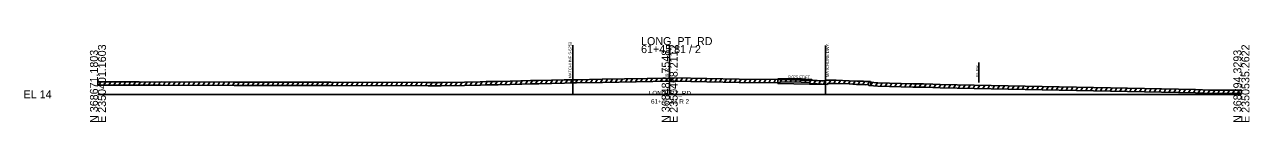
# Model space of a CAD drawing. Extents: x 974 to 2350744, y -10 to 368509.
# Drawn here: x 1974.3 to 2402.8, y 5990.3 to 6020.1 of the extents above; entities that cross this region are included whole.
import ezdxf

# ---------------------------------------------------------------- set-up
doc = ezdxf.new("R2010")
doc.units = 0
for name, color, linetype in [('RD_GPK_XS_Cell', 7, 'Continuous'), ('RD_XS_Base', 7, 'Continuous'), ('RD_XS_ExGround', 7, 'Continuous'), ('RD_XS_ExPaveRet', 7, 'Continuous'), ('RD_XS_ExRW', 7, 'Continuous'), ('RD_XS_MatchLine', 7, 'Continuous'), ('RD_XS_Pave', 7, 'Continuous'), ('RD_XS_TX_Elev_EX', 7, 'Continuous'), ('RD_XS_TX_Slope', 7, 'Continuous'), ('RD_XS_TX_Station', 7, 'Continuous')]:
    doc.layers.add(name, color=color, linetype=linetype)

msp = doc.modelspace()

# ---------------------------------------------------------------- linework, layer by layer
at = {"layer": 'RD_GPK_XS_Cell'}
for p, q in [((2200, 6000), (2200, 6017.25)), ((2000, 6000), (2200, 6000)), ((2200, 6000), (2400, 6000))]:
    msp.add_line(p, q, dxfattribs=at)
at = {"layer": 'RD_XS_Base'}
for p, q in [((2237.82, 6003.82), (2237.82, 6005.16)), ((2237.82, 6003.82), (2254.52, 6003.41)), ((2254.52, 6003.41), (2254.52, 6004.75))]:
    msp.add_line(p, q, dxfattribs=at)
at = {"layer": 'RD_XS_ExGround'}
msp.add_lwpolyline([(2000, 6004.41), (2007.21, 6004.37), (2014.41, 6004.37), (2015.38, 6004.31), (2022.11, 6004.38), (2047.62, 6004.26), (2053.58, 6004.25), (2057.29, 6004.24), (2080.97, 6004.21), (2081.44, 6004.21), (2115.47, 6004.12), (2120.02, 6004.16), (2128.26, 6004.3), (2133.76, 6004.38), (2135.8, 6004.48), (2139.62, 6004.5), (2140, 6004.51), (2144.22, 6004.58), (2147.95, 6004.68), (2148.26, 6004.7), (2151.36, 6004.81), (2154.18, 6004.86), (2163.15, 6005.08), (2165.49, 6005.14), (2167.39, 6005.14), (2176.43, 6005.3), (2200, 6005.72), (2201.67, 6005.75), (2224.34, 6005.29), (2237.82, 6005.16), (2237.98, 6005.46), (2238.34, 6005.46), (2241.38, 6005.48), (2246.08, 6005.4), (2249.32, 6005.24), (2249.68, 6005.24), (2249.84, 6004.94), (2251.62, 6004.83), (2254.52, 6004.67), (2254.68, 6004.97), (2255.03, 6004.97), (2256.6, 6004.95), (2258.25, 6004.92), (2262.79, 6004.79), (2265.42, 6004.64), (2267.84, 6004.6), (2268.58, 6004.53), (2269.1, 6004.55), (2269.87, 6004.52), (2270.24, 6004.51), (2270.4, 6004.21), (2271.42, 6004.15), (2272.85, 6004.05), (2285.05, 6003.69), (2286.57, 6003.65), (2288.8, 6003.63), (2292.09, 6003.51), (2294.62, 6003.45), (2384, 6001.69), (2388.96, 6001.47), (2392.65, 6001.47), (2400, 6001.43)], dxfattribs=at)
at = {"layer": 'RD_XS_ExPaveRet'}
for p, q in [((2000, 6003.27), (2000, 6004.41)), ((2000.38, 6003.26), (2001.04, 6004.4)), ((2002.11, 6003.26), (2002.77, 6004.4)), ((2003.84, 6003.25), (2004.5, 6004.39)), ((2005.56, 6003.24), (2006.22, 6004.38)), ((2007.29, 6003.23), (2007.95, 6004.37)), ((2009.02, 6003.23), (2009.68, 6004.37)), ((2010.75, 6003.23), (2011.41, 6004.37)), ((2012.49, 6003.23), (2013.15, 6004.37)), ((2014.22, 6003.23), (2014.86, 6004.34)), ((2015.92, 6003.18), (2016.58, 6004.33)), ((2017.66, 6003.19), (2018.33, 6004.34)), ((2019.41, 6003.21), (2020.07, 6004.36)), ((2021.15, 6003.23), (2021.81, 6004.38)), ((2022.88, 6003.24), (2023.54, 6004.38)), ((2024.61, 6003.23), (2025.27, 6004.37)), ((2026.34, 6003.22), (2027, 6004.36)), ((2028.07, 6003.21), (2028.72, 6004.35)), ((2029.79, 6003.2), (2030.45, 6004.34)), ((2031.52, 6003.2), (2032.18, 6004.34)), ((2033.25, 6003.19), (2033.91, 6004.33)), ((2034.98, 6003.18), (2035.63, 6004.32)), ((2036.7, 6003.17), (2037.36, 6004.31)), ((2038.43, 6003.16), (2039.09, 6004.3)), ((2040.16, 6003.16), (2040.82, 6004.3)), ((2041.89, 6003.15), (2042.54, 6004.29)), ((2043.61, 6003.14), (2044.27, 6004.28)), ((2045.34, 6003.13), (2046, 6004.27)), ((2047.07, 6003.12), (2047.73, 6004.26)), ((2048.8, 6003.12), (2049.46, 6004.26)), ((2050.53, 6003.11), (2051.18, 6004.25)), ((2052.26, 6003.11), (2052.91, 6004.25)), ((2053.98, 6003.1), (2054.64, 6004.25)), ((2055.72, 6003.1), (2056.37, 6004.24)), ((2057.45, 6003.1), (2058.11, 6004.24)), ((2059.18, 6003.1), (2059.84, 6004.24)), ((2060.91, 6003.09), (2061.57, 6004.24)), ((2062.64, 6003.09), (2063.3, 6004.23)), ((2064.37, 6003.09), (2065.03, 6004.23)), ((2066.1, 6003.09), (2066.76, 6004.23)), ((2067.83, 6003.08), (2068.49, 6004.23)), ((2069.56, 6003.08), (2070.22, 6004.22)), ((2071.29, 6003.08), (2071.95, 6004.22)), ((2073.02, 6003.08), (2073.68, 6004.22)), ((2074.75, 6003.07), (2075.41, 6004.21)), ((2076.48, 6003.07), (2077.14, 6004.21)), ((2078.21, 6003.07), (2078.87, 6004.21)), ((2079.94, 6003.06), (2080.6, 6004.21)), ((2081.67, 6003.06), (2082.33, 6004.2)), ((2083.4, 6003.06), (2084.06, 6004.2)), ((2085.13, 6003.05), (2085.79, 6004.19)), ((2086.86, 6003.05), (2087.52, 6004.19)), ((2088.59, 6003.05), (2089.25, 6004.19)), ((2090.32, 6003.04), (2090.98, 6004.18)), ((2092.05, 6003.04), (2092.71, 6004.18)), ((2093.78, 6003.03), (2094.44, 6004.17)), ((2095.51, 6003.03), (2096.17, 6004.17)), ((2097.24, 6003.02), (2097.9, 6004.17)), ((2098.97, 6003.02), (2099.63, 6004.16)), ((2100.7, 6003.02), (2101.36, 6004.16)), ((2102.43, 6003.01), (2103.09, 6004.15)), ((2104.16, 6003.01), (2104.82, 6004.15)), ((2105.89, 6003), (2106.55, 6004.15)), ((2107.62, 6003), (2108.28, 6004.14)), ((2109.35, 6003), (2110.01, 6004.14)), ((2111.08, 6002.99), (2111.74, 6004.13)), ((2112.81, 6002.99), (2113.47, 6004.13)), ((2114.54, 6002.98), (2115.2, 6004.13)), ((2116.27, 6002.99), (2116.93, 6004.13)), ((2118.01, 6003), (2118.67, 6004.15)), ((2119.75, 6003.01), (2120.41, 6004.16)), ((2121.5, 6003.04), (2122.16, 6004.19)), ((2123.25, 6003.07), (2123.91, 6004.22)), ((2124.99, 6003.1), (2125.66, 6004.25)), ((2126.74, 6003.13), (2127.41, 6004.28)), ((2128.49, 6003.16), (2129.16, 6004.31)), ((2130.24, 6003.18), (2130.91, 6004.34)), ((2131.99, 6003.21), (2132.65, 6004.36)), ((2133.73, 6003.23), (2134.41, 6004.41)), ((2135.52, 6003.32), (2136.19, 6004.48)), ((2137.26, 6003.35), (2137.92, 6004.49)), ((2139, 6003.36), (2139.66, 6004.5)), ((2140.74, 6003.38), (2141.41, 6004.53)), ((2142.49, 6003.41), (2143.16, 6004.56)), ((2144.24, 6003.44), (2144.91, 6004.6)), ((2146, 6003.48), (2146.67, 6004.64)), ((2147.76, 6003.53), (2148.44, 6004.71)), ((2149.53, 6003.6), (2150.21, 6004.77)), ((2151.3, 6003.66), (2151.97, 6004.82)), ((2153.05, 6003.7), (2153.72, 6004.85)), ((2154.81, 6003.73), (2155.48, 6004.89)), ((2156.56, 6003.78), (2157.23, 6004.94)), ((2158.32, 6003.82), (2158.99, 6004.98)), ((2160.08, 6003.86), (2160.75, 6005.02)), ((2161.83, 6003.9), (2162.5, 6005.06)), ((2163.59, 6003.94), (2164.26, 6005.11)), ((2165.35, 6003.99), (2166.01, 6005.14)), ((2167.08, 6003.99), (2167.74, 6005.14)), ((2168.83, 6004.02), (2169.49, 6005.17)), ((2170.58, 6004.05), (2171.25, 6005.21)), ((2172.33, 6004.08), (2173, 6005.24)), ((2174.08, 6004.11), (2174.75, 6005.27)), ((2175.83, 6004.15), (2176.5, 6005.3)), ((2177.58, 6004.18), (2178.25, 6005.33)), ((2179.33, 6004.21), (2180, 6005.36)), ((2181.08, 6004.24), (2181.75, 6005.39)), ((2182.83, 6004.27), (2183.5, 6005.43)), ((2184.58, 6004.3), (2185.25, 6005.46)), ((2186.33, 6004.33), (2187, 6005.49)), ((2188.08, 6004.36), (2188.75, 6005.52)), ((2189.83, 6004.4), (2190.5, 6005.55)), ((2191.58, 6004.43), (2192.25, 6005.58)), ((2193.33, 6004.46), (2194, 6005.61)), ((2195.08, 6004.49), (2195.75, 6005.64)), ((2196.83, 6004.52), (2197.5, 6005.68)), ((2198.58, 6004.55), (2199.25, 6005.71)), ((2200.33, 6004.58), (2201, 6005.74)), ((2202.07, 6004.6), (2202.72, 6005.73)), ((2203.78, 6004.57), (2204.44, 6005.7)), ((2205.5, 6004.53), (2206.15, 6005.66)), ((2207.21, 6004.5), (2207.86, 6005.63)), ((2208.92, 6004.46), (2209.57, 6005.59)), ((2210.63, 6004.43), (2211.29, 6005.56)), ((2212.34, 6004.39), (2213, 6005.52)), ((2214.06, 6004.36), (2214.71, 6005.49)), ((2215.77, 6004.32), (2216.42, 6005.45)), ((2217.48, 6004.29), (2218.13, 6005.42)), ((2219.19, 6004.25), (2219.85, 6005.38)), ((2220.91, 6004.22), (2221.56, 6005.35)), ((2222.62, 6004.18), (2223.27, 6005.31)), ((2224.33, 6004.15), (2224.99, 6005.29)), ((2226.05, 6004.13), (2226.71, 6005.27)), ((2227.77, 6004.12), (2228.43, 6005.25)), ((2229.5, 6004.1), (2230.15, 6005.24)), ((2231.22, 6004.08), (2231.88, 6005.22)), ((2232.94, 6004.07), (2233.6, 6005.2)), ((2234.66, 6004.05), (2235.32, 6005.19)), ((2236.39, 6004.03), (2237.04, 6005.17)), ((2237.82, 6005.16), (2237.82, 6004.02)), ((2238.49, 6004.01), (2238.6, 6004.19)), ((2238.67, 6004.32), (2239.33, 6005.47)), ((2240.41, 6004.33), (2241.07, 6005.48)), ((2242.13, 6004.32), (2242.79, 6005.46)), ((2243.85, 6004.29), (2244.5, 6005.43)), ((2245.56, 6004.27), (2246.22, 6005.39)), ((2247.26, 6004.2), (2247.9, 6005.31)), ((2248.94, 6004.12), (2249.59, 6005.24)), ((2250.47, 6003.76), (2251.11, 6004.86)), ((2252.14, 6003.66), (2252.78, 6004.77)), ((2253.82, 6003.57), (2254.46, 6004.68)), ((2255.7, 6003.82), (2256.35, 6004.95)), ((2257.41, 6003.79), (2258.07, 6004.92)), ((2259.12, 6003.75), (2259.77, 6004.87)), ((2260.83, 6003.7), (2261.48, 6004.83)), ((2262.53, 6003.65), (2263.18, 6004.77)), ((2264.21, 6003.57), (2264.85, 6004.67)), ((2265.9, 6003.49), (2266.55, 6004.62)), ((2267.61, 6003.46), (2268.25, 6004.56)), ((2269.31, 6003.4), (2269.96, 6004.52)), ((2270.4, 6004.21), (2270.4, 6003.06)), ((2270.4, 6003.17), (2270.99, 6004.18)), ((2272.02, 6002.97), (2272.65, 6004.07)), ((2273.7, 6002.88), (2274.35, 6004.01)), ((2275.41, 6002.83), (2276.06, 6003.96)), ((2277.11, 6002.78), (2277.76, 6003.91)), ((2278.81, 6002.73), (2279.46, 6003.86)), ((2280.52, 6002.68), (2281.17, 6003.81)), ((2282.22, 6002.63), (2282.87, 6003.76)), ((2283.92, 6002.58), (2284.57, 6003.71)), ((2285.63, 6002.53), (2286.28, 6003.66)), ((2287.34, 6002.5), (2287.99, 6003.63)), ((2289.06, 6002.47), (2289.7, 6003.6)), ((2290.75, 6002.42), (2291.4, 6003.54)), ((2292.45, 6002.36), (2293.11, 6003.49)), ((2294.16, 6002.32), (2294.81, 6003.45)), ((2295.87, 6002.28), (2296.53, 6003.41)), ((2297.59, 6002.25), (2298.24, 6003.38)), ((2299.3, 6002.22), (2299.95, 6003.35)), ((2301.01, 6002.18), (2301.66, 6003.31)), ((2302.72, 6002.15), (2303.38, 6003.28)), ((2304.44, 6002.12), (2305.09, 6003.25)), ((2306.15, 6002.08), (2306.8, 6003.21)), ((2307.86, 6002.05), (2308.51, 6003.18)), ((2309.57, 6002.01), (2310.23, 6003.14)), ((2311.29, 6001.98), (2311.94, 6003.11)), ((2313, 6001.95), (2313.65, 6003.08)), ((2314.71, 6001.91), (2315.36, 6003.04)), ((2316.42, 6001.88), (2317.08, 6003.01)), ((2318.14, 6001.84), (2318.79, 6002.98)), ((2319.85, 6001.81), (2320.5, 6002.94)), ((2321.56, 6001.78), (2322.21, 6002.91)), ((2323.27, 6001.74), (2323.93, 6002.87)), ((2324.99, 6001.71), (2325.64, 6002.84)), ((2326.7, 6001.68), (2327.35, 6002.81)), ((2328.41, 6001.64), (2329.07, 6002.77)), ((2330.13, 6001.61), (2330.78, 6002.74)), ((2331.84, 6001.57), (2332.49, 6002.7)), ((2333.55, 6001.54), (2334.2, 6002.67)), ((2335.26, 6001.51), (2335.92, 6002.64)), ((2336.98, 6001.47), (2337.63, 6002.6)), ((2338.69, 6001.44), (2339.34, 6002.57)), ((2340.4, 6001.41), (2341.05, 6002.54)), ((2342.11, 6001.37), (2342.77, 6002.5)), ((2343.83, 6001.34), (2344.48, 6002.47)), ((2345.54, 6001.3), (2346.19, 6002.43)), ((2347.25, 6001.27), (2347.9, 6002.4)), ((2348.96, 6001.24), (2349.62, 6002.37)), ((2350.68, 6001.2), (2351.33, 6002.33)), ((2352.39, 6001.17), (2353.04, 6002.3)), ((2354.1, 6001.13), (2354.75, 6002.27)), ((2355.81, 6001.1), (2356.47, 6002.23)), ((2357.53, 6001.07), (2358.18, 6002.2)), ((2359.24, 6001.03), (2359.89, 6002.16)), ((2360.95, 6001), (2361.6, 6002.13)), ((2362.66, 6000.97), (2363.32, 6002.1)), ((2364.38, 6000.93), (2365.03, 6002.06)), ((2366.09, 6000.9), (2366.74, 6002.03)), ((2367.8, 6000.86), (2368.45, 6001.99)), ((2369.51, 6000.83), (2370.17, 6001.96)), ((2371.23, 6000.8), (2371.88, 6001.93)), ((2372.94, 6000.76), (2373.59, 6001.89)), ((2374.65, 6000.73), (2375.3, 6001.86)), ((2376.36, 6000.7), (2377.02, 6001.83)), ((2378.08, 6000.66), (2378.73, 6001.79)), ((2379.79, 6000.63), (2380.44, 6001.76)), ((2381.5, 6000.59), (2382.15, 6001.72)), ((2383.21, 6000.56), (2383.87, 6001.69)), ((2384.91, 6000.5), (2385.56, 6001.62)), ((2386.6, 6000.43), (2387.25, 6001.55)), ((2388.29, 6000.36), (2388.94, 6001.47)), ((2390.01, 6000.33), (2390.67, 6001.47)), ((2391.74, 6000.33), (2392.4, 6001.47)), ((2393.47, 6000.33), (2394.13, 6001.47)), ((2395.2, 6000.32), (2395.85, 6001.45)), ((2396.92, 6000.31), (2397.58, 6001.44)), ((2398.65, 6000.29), (2399.31, 6001.43)), ((2400, 6000.29), (2400, 6001.43))]:
    msp.add_line(p, q, dxfattribs=at)
for points in [[(1999.99, 6003.27), (2007.2, 6003.23), (2014.38, 6003.23), (2015.35, 6003.17), (2022.12, 6003.24), (2047.62, 6003.12), (2053.57, 6003.11), (2057.28, 6003.1), (2080.97, 6003.06), (2081.44, 6003.06), (2115.47, 6002.98), (2120.03, 6003.01), (2128.28, 6003.15), (2133.8, 6003.24), (2135.83, 6003.34), (2139.62, 6003.36), (2140.01, 6003.36), (2144.25, 6003.44), (2148.01, 6003.53), (2148.32, 6003.56), (2151.39, 6003.67), (2154.2, 6003.72), (2163.18, 6003.93), (2165.51, 6004), (2167.4, 6003.99), (2176.45, 6004.16), (2200.02, 6004.58), (2201.67, 6004.61), (2224.32, 6004.15), (2237.82, 6004.02)], [(2237.82, 6004.02), (2238.5, 6004.01), (2238.66, 6004.32), (2241.37, 6004.34), (2246.04, 6004.26), (2248.98, 6004.11), (2249.13, 6003.84), (2251.55, 6003.69), (2255.18, 6003.49), (2255.36, 6003.83), (2256.58, 6003.81), (2258.23, 6003.77), (2262.74, 6003.65), (2265.38, 6003.5), (2267.78, 6003.45), (2268.56, 6003.39), (2269.1, 6003.41), (2269.55, 6003.39), (2269.71, 6003.1), (2270.4, 6003.06)], [(2270.4, 6003.06), (2271.35, 6003.01), (2272.79, 6002.91), (2285.02, 6002.55), (2286.54, 6002.51), (2288.77, 6002.48), (2292.05, 6002.37), (2294.59, 6002.31), (2383.97, 6000.55), (2388.93, 6000.33), (2392.65, 6000.33), (2400, 6000.29)]]:
    msp.add_lwpolyline(points, dxfattribs=at)
at = {"layer": 'RD_XS_ExRW'}
msp.add_line((2308.18, 6004.18), (2308.18, 6011.18), dxfattribs=at)
at = {"layer": 'RD_XS_MatchLine'}
for p, q in [((2166.15, 6017.25), (2166.15, 6000)), ((2254.52, 6017.17), (2254.52, 5999.91)), ((2166.15, 6004.98), (2166.15, 6005.14))]:
    msp.add_line(p, q, dxfattribs=at)
at = {"layer": 'RD_XS_Pave'}
msp.add_line((2237.82, 6005.16), (2254.52, 6004.75), dxfattribs=at)

# ---------------------------------------------------------------- texts
at = {"layer": 'RD_GPK_XS_Cell'}
for s, p in [('E 2350401.1603', (2002.8, 5990)), ('E 2350468.2112', (2202.8, 5990)), ('E 2350535.2622', (2402.8, 5990)), ('N 368671.1803', (2000, 5990)), ('N 368482.7548', (2200, 5990)), ('N 368294.3293', (2400, 5990))]:
    msp.add_text(s, height=2.8, rotation=90, dxfattribs=at).set_placement(p)
for s, p in [('61+45.81 / 2', (2190, 6014.45)), ('LONG_PT_RD', (2190, 6017.25)), ('EL 14', (1974, 5998.6))]:
    msp.add_text(s, height=2.8, dxfattribs=at).set_placement(p)
at = {"layer": 'RD_XS_ExRW'}
msp.add_text('EX. R/W ', height=0.75, rotation=90, dxfattribs=at).set_placement((2307.92, 6006.14))
at = {"layer": 'RD_XS_MatchLine'}
for s, p in [('MATCHLINE S-5253', (2165.66, 6005.58)), ('MATCHLINE DWY.', (2255.73, 6006.06))]:
    msp.add_text(s, height=1, rotation=90, dxfattribs=at).set_placement(p)
at = {"layer": 'RD_XS_TX_Elev_EX'}
msp.add_text('19.72', height=1, rotation=90, dxfattribs=at).set_placement((2199.51, 6005.72))
at = {"layer": 'RD_XS_TX_Slope'}
msp.add_text('0.025 FT/FT', height=1, rotation=358.5679, dxfattribs=at).set_placement((2241.48, 6005.69))
at = {"layer": 'RD_XS_TX_Station'}
for s, p in [('LONG_PT_RD', (2192.72, 5999.62)), ('61+45.81 R 2', (2193.48, 5996.72))]:
    msp.add_text(s, height=1.6, dxfattribs=at).set_placement(p)

doc.saveas('drawing.dxf')
